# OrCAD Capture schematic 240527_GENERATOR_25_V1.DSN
size A4; title: GNERATOR_25_V1; rev: 1.0; note: ELECTRONIC CAD_2024.05.27
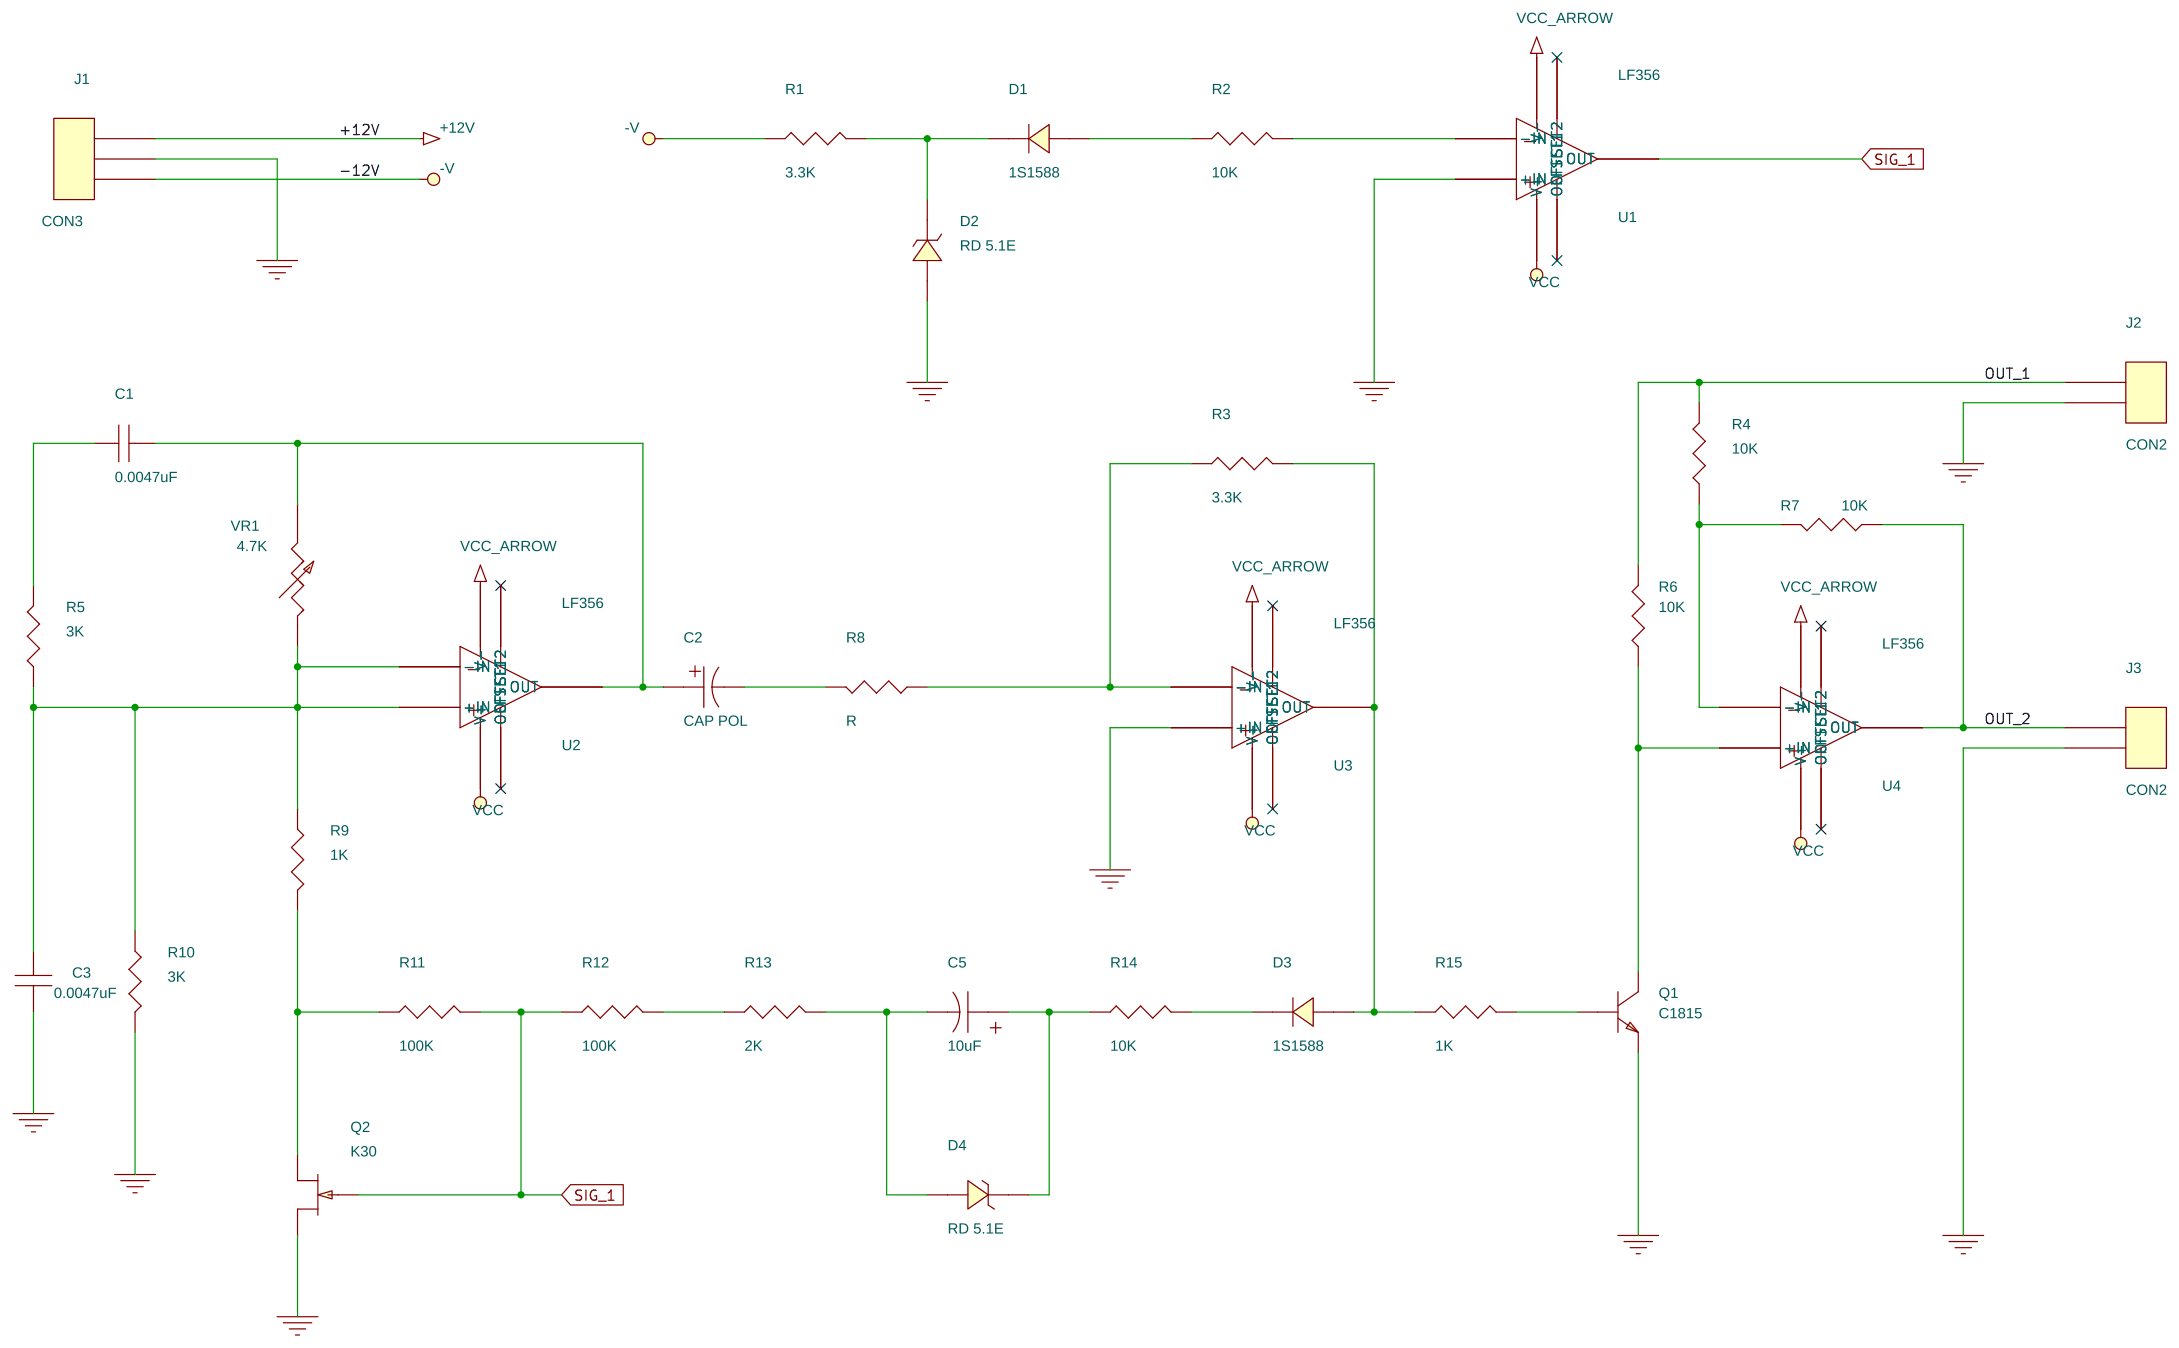
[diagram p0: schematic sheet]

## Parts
C1  0.0047uF  [CAPCK05]
C2  CAP POL  [CAP196]
C3  0.0047uF  [CAPCK05]
C5  10uF  [CAP196]
D1  1S1588  [DO41]
D2  RD 5.1E  [DO41]
D3  1S1588  [DO41]
D4  RD 5.1E  [DO41]
J1  CON3  [CON3]
J2  CON2  [CON2]
J3  CON2  [CON2]
Q1  C1815  [TO92]
Q2  K30  [TO92]
R1  3.3K  [RES400]
R2  10K  [RES400]
R3  3.3K  [RES400]
R4  10K  [RES400]
R5  3K  [RES400]
R6  10K  [RES400]
R7  10K  [RES400]
R8  R  [RES400]
R9  1K  [RES400]
R10  3K  [RES400]
R11  100K  [RES400]
R12  100K  [RES400]
R13  2K  [RES400]
R14  10K  [RES400]
R15  1K  [RES400]
U1  LF356  [DIP8_3]
U2  LF356  [DIP8_3]
U3  LF356  [DIP8_3]
U4  LF356  [DIP8_3]
VR1  4.7K  [RESADJ]

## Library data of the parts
C1 C3 = CAP_NP
C2 C5 = CAP_POL
D1 D3 = DIODE
D2 D4 = DIODE_ZENER
J1 = CON3
J2 J3 = CON2
Q1 = NPN_ECB
Q2 = JFET_N_SDG
R1-R15 = R
U1-U4 = LF356: NC: 8
VR1 = RESISTOR_VAR_2: NC: 3

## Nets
GND: C3.2 D2.2(ANODE) J1.2 J2.2 J3.2 Q1.1(E) Q2.2(D) R10.2 U1.3(+IN) U3.3(+IN)
+V: J1.1 U1.4(V-) U2.4(V-) U3.4(V-) U4.4(V-)
-V: J1.3 R1.1 U1.7(V+) U2.7(V+) U3.7(V+) U4.7(V+)
OUT_1: J2.1 R4.2 R6.2
OUT_2: J3.1 R7.1 U4.6(OUT)
SIG_1: Q2.3(G) R11.2 R12.1 U1.6(OUT)
N01616: D1.1(K) D2.1(CATHODE) R1.2
N01636: D1.2(A) R2.1
N01640: R2.2 U1.2(-IN)
N01654: R3.1 R8.1 U3.2(-IN)
N01670: C2.2 R8.2
N01674: C1.2 C2.1 U2.6(OUT) VR1.2
N01678: C3.1 R5.1 R9.1 R10.1 U2.2(-IN) U2.3(+IN) VR1.1
N01713: C1.1 R5.2
N01735: Q2.1(S) R9.2 R11.1
N01746: R12.2 R13.1
N01750: C5.2 D4.2(ANODE) R13.2
N01754: C5.1 D4.1(CATHODE) R14.1
N01758: D3.1(K) R14.2
N01762: D3.2(A) R3.2 R15.1 U3.6(OUT)
N01766: Q1.3(B) R15.2
N02360: Q1.2(C) R6.1 U4.3(+IN)
N02374: R4.1 R7.2 U4.2(-IN)

Not connected (* = marked no-connect by the designer): U1 1(OFFSET1)* 5(OFFSET2)*; U2 1(OFFSET1)* 5(OFFSET2)*; U3 1(OFFSET1)* 5(OFFSET2)*; U4 1(OFFSET1)* 5(OFFSET2)*
